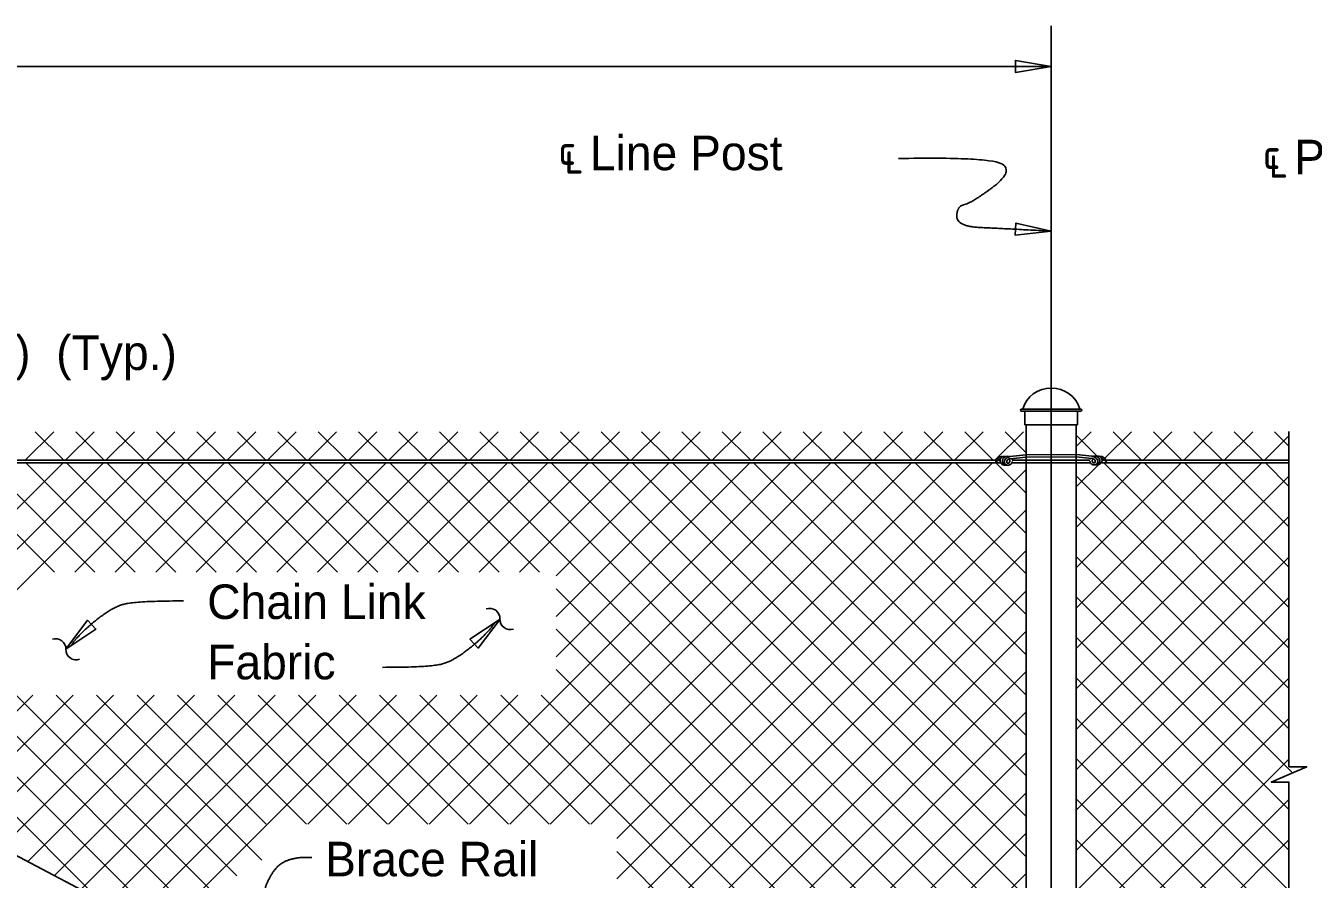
# Model space of a CAD drawing. Extents: x 0.5 to 39.7, y 0.9 to 25.6.
# Drawn here: x 16.23 to 23.73, y 20.53 to 25.5 of the extents above; entities that cross this region are included whole.
import ezdxf

# ---------------------------------------------------------------- set-up
doc = ezdxf.new("R2010")
doc.units = 0
for name, color, linetype in [('CL_Major', 7, 'Continuous'), ('Dimension', 7, 'Continuous'), ('Miscellaneous', 7, 'Continuous'), ('SteelMisc', 7, 'Continuous'), ('SteelMisc_h', 7, 'Continuous'), ('TextStructures', 7, 'Continuous')]:
    doc.layers.add(name, color=color, linetype=linetype)

msp = doc.modelspace()

# ---------------------------------------------------------------- linework, layer by layer
at = {"layer": 'CL_Major'}
msp.add_line((22.2062, 25.5043), (22.2062, 14.6639), dxfattribs=at)
at = {"layer": 'Dimension'}
msp.add_line((2.2062, 25.2672), (22.2062, 25.2672), dxfattribs=at)
for points in [[(22.2062, 25.2672), (21.998, 25.3025), (21.998, 25.2319)], [(22.2062, 24.3062), (22.0002, 24.3528), (21.9964, 24.2823)], [(16.4595, 21.8673), (16.6347, 21.9852), (16.5861, 22.0364)], [(18.9917, 22.0434), (18.8164, 21.9255), (18.865, 21.8743)]]:
    msp.add_lwpolyline(points, close=True, dxfattribs=at)
msp.add_lwpolyline([(23.5932, 23.1382), (23.5932, 21.1819), (23.6966, 21.1819), (23.5932, 21.1369), (23.4899, 21.0919), (23.5932, 21.0919), (23.5932, 20.1983)], dxfattribs=at)
for centre, start, end in [((18.9315, 22.0462), 357.71778, 109.44499), ((19.0506, 22.0414), 177.71778, 289.44499), ((16.4004, 21.8692), 357.71778, 109.44499), ((16.5195, 21.8645), 177.71778, 289.44499)]:
    msp.add_arc(centre, 0.0596, start, end, dxfattribs=at)
for points in [[(21.3167, 24.7299), (21.8625, 24.7397), (21.9849, 24.6508), (21.7407, 24.4695), (21.6558, 24.4512), (21.6558, 24.3333), (21.9339, 24.321), (22.2062, 24.3061)], [(17.1447, 22.149), (16.8545, 22.149), (16.7179, 22.1042), (16.5309, 21.9506), (16.4925, 21.893)], [(18.3063, 21.7616), (18.5965, 21.7616), (18.7331, 21.8064), (18.9201, 21.96), (18.9585, 22.0176)], [(17.894, 20.6524), (17.7375, 20.6606), (17.6194, 20.5021), (17.6164, 20.3809), (17.6211, 20.2132), (17.6839, 19.8645)]]:
    msp.add_open_spline(points, degree=2, dxfattribs=at)
at = {"layer": 'Miscellaneous'}
for p, q in [((16.2217, 22.9695), (16.3884, 23.1361)), ((16.281, 23.1361), (16.4476, 22.9695)), ((16.4575, 22.9695), (16.6241, 23.1361)), ((16.5167, 23.1361), (16.6833, 22.9695)), ((16.6932, 22.9695), (16.8598, 23.1361)), ((16.7524, 23.1361), (16.919, 22.9695)), ((16.9289, 22.9695), (17.0955, 23.1361)), ((16.9881, 23.1361), (17.1547, 22.9695)), ((17.1646, 22.9695), (17.3312, 23.1361)), ((17.2238, 23.1361), (17.3904, 22.9695)), ((17.4003, 22.9695), (17.5669, 23.1361)), ((17.4595, 23.1361), (17.6262, 22.9695)), ((17.636, 22.9695), (17.8026, 23.1361)), ((17.6952, 23.1361), (17.8619, 22.9695)), ((17.8717, 22.9695), (18.0383, 23.1361)), ((17.9309, 23.1361), (18.0976, 22.9695)), ((18.1074, 22.9695), (18.274, 23.1361)), ((18.1666, 23.1361), (18.3333, 22.9695)), ((18.3431, 22.9695), (18.5097, 23.1361)), ((18.4023, 23.1361), (18.569, 22.9695)), ((18.5788, 22.9695), (18.7454, 23.1361)), ((18.638, 23.1361), (18.8047, 22.9695)), ((18.8145, 22.9695), (18.9811, 23.1361)), ((18.8737, 23.1361), (19.0404, 22.9695)), ((19.0502, 22.9695), (19.2168, 23.1361)), ((19.1094, 23.1361), (19.2761, 22.9695)), ((19.2859, 22.9695), (19.4525, 23.1361)), ((19.3451, 23.1361), (19.5118, 22.9695)), ((19.5216, 22.9695), (19.6882, 23.1361)), ((19.5808, 23.1361), (19.7475, 22.9695)), ((19.7573, 22.9695), (19.9239, 23.1361)), ((19.8165, 23.1361), (19.9832, 22.9695)), ((19.993, 22.9695), (20.1597, 23.1361)), ((20.0522, 23.1361), (20.2189, 22.9695)), ((20.2287, 22.9695), (20.3954, 23.1361)), ((20.2879, 23.1361), (20.4546, 22.9695)), ((20.4644, 22.9695), (20.6311, 23.1361)), ((20.5236, 23.1361), (20.6903, 22.9695)), ((20.7001, 22.9695), (20.8668, 23.1361)), ((20.7593, 23.1361), (20.926, 22.9695)), ((20.9358, 22.9695), (21.1025, 23.1361)), ((20.995, 23.1361), (21.1617, 22.9695)), ((21.1715, 22.9695), (21.3382, 23.1361)), ((21.2307, 23.1361), (21.3974, 22.9695)), ((21.4072, 22.9695), (21.5739, 23.1361)), ((21.4664, 23.1361), (21.6331, 22.9695)), ((21.6429, 22.9695), (21.8096, 23.1361)), ((21.7021, 23.1361), (21.8688, 22.9695)), ((21.8786, 22.9695), (22.0453, 23.1361)), ((21.9378, 23.1361), (22.0604, 23.0136)), ((22.3521, 23.0495), (22.4386, 23.1361)), ((22.5192, 22.981), (22.6743, 23.1361)), ((22.5669, 23.1361), (22.7336, 22.9695)), ((22.7434, 22.9695), (22.91, 23.1361)), ((22.8026, 23.1361), (22.9693, 22.9695)), ((22.9791, 22.9695), (23.1458, 23.1361)), ((23.0383, 23.1361), (23.205, 22.9695)), ((23.2148, 22.9695), (23.3815, 23.1361)), ((23.274, 23.1361), (23.4407, 22.9695)), ((23.5097, 23.1361), (23.5931, 23.0527)), ((22.3521, 23.1153), (22.4743, 22.993)), ((23.4505, 22.9695), (23.5931, 23.1121)), ((14.1054, 22.9547), (16.6484, 20.4117)), ((14.3411, 22.9547), (17.1483, 20.1475)), ((14.5768, 22.9547), (17.4573, 20.0742)), ((14.8125, 22.9547), (17.4573, 20.3099)), ((14.85, 21.362), (16.4427, 22.9547)), ((15.0042, 21.2805), (16.6784, 22.9547)), ((15.1584, 21.199), (16.9141, 22.9547)), ((15.7553, 22.9547), (16.393, 22.317)), ((15.991, 22.9547), (16.6287, 22.317)), ((16.2267, 22.9547), (16.8644, 22.317)), ((16.4624, 22.9547), (17.1001, 22.317)), ((16.5121, 22.317), (17.1498, 22.9547)), ((16.6981, 22.9547), (17.3358, 22.317)), ((16.7478, 22.317), (17.3855, 22.9547)), ((16.9338, 22.9547), (17.5715, 22.317)), ((16.9835, 22.317), (17.6212, 22.9547)), ((17.1695, 22.9547), (17.8072, 22.317)), ((17.2192, 22.317), (17.8569, 22.9547)), ((17.4052, 22.9547), (18.0429, 22.317)), ((17.4549, 22.317), (18.0926, 22.9547)), ((17.6409, 22.9547), (18.2786, 22.317)), ((17.6906, 22.317), (18.3283, 22.9547)), ((17.8766, 22.9547), (18.5143, 22.317)), ((17.9263, 22.317), (18.564, 22.9547)), ((18.1123, 22.9547), (18.75, 22.317)), ((18.162, 22.317), (18.7997, 22.9547)), ((18.348, 22.9547), (18.9857, 22.317)), ((18.3977, 22.317), (19.0354, 22.9547)), ((18.5775, 20.8468), (20.6853, 22.9547)), ((18.5837, 22.9547), (19.2214, 22.317)), ((18.6334, 22.317), (19.2711, 22.9547)), ((18.8132, 20.8468), (20.921, 22.9547)), ((18.8194, 22.9547), (22.0604, 19.7137)), ((18.8691, 22.317), (19.5068, 22.9547)), ((19.0489, 20.8468), (21.1567, 22.9547)), ((19.0551, 22.9547), (22.0604, 19.9494)), ((19.1049, 22.317), (19.7425, 22.9547)), ((19.2846, 20.8468), (21.3924, 22.9547)), ((19.2908, 22.9547), (22.0604, 20.1851)), ((19.3184, 22.2948), (19.9782, 22.9547)), ((19.3184, 21.8234), (20.4496, 22.9547)), ((19.3184, 22.0591), (20.2139, 22.9547)), ((19.5203, 20.8468), (21.6282, 22.9547)), ((19.5203, 20.8468), (21.6282, 22.9547)), ((19.5265, 22.9547), (22.0604, 20.4208)), ((19.6731, 20.7639), (21.8639, 22.9547)), ((19.6731, 20.5282), (22.0604, 22.9155)), ((19.7622, 22.9547), (22.0604, 20.6565)), ((19.9979, 22.9547), (22.0604, 20.8922)), ((20.2336, 22.9547), (22.0604, 21.1279)), ((20.4693, 22.9547), (22.0604, 21.3636)), ((20.705, 22.9547), (22.0604, 21.5993)), ((20.9407, 22.9547), (22.0604, 21.835)), ((21.1764, 22.9547), (22.0604, 22.0707)), ((21.4121, 22.9547), (22.0604, 22.3064)), ((21.6478, 22.9547), (22.0604, 22.5421)), ((21.8835, 22.9547), (22.0604, 22.7779)), ((22.3521, 21.871), (23.4357, 22.9547)), ((22.3521, 22.3424), (22.9643, 22.9547)), ((22.3521, 22.5781), (22.7286, 22.9547)), ((22.3521, 22.8138), (22.4815, 22.9433)), ((22.3565, 22.1112), (23.2, 22.9547)), ((22.5077, 22.9695), (22.5121, 22.9739)), ((22.5126, 22.9547), (23.5931, 21.8742)), ((22.7483, 22.9547), (23.5931, 22.1099)), ((22.984, 22.9547), (23.5931, 22.3456)), ((23.2197, 22.9547), (23.5931, 22.5813)), ((23.4554, 22.9547), (23.5931, 22.817)), ((22.3521, 22.8796), (23.5931, 21.6385)), ((22.3521, 21.6353), (23.5931, 22.8764)), ((18.7053, 19.3247), (22.0604, 22.6798)), ((22.3521, 22.6439), (23.5931, 21.4028)), ((22.3521, 21.3996), (23.5931, 22.6407)), ((18.8595, 19.2432), (22.0604, 22.4441)), ((22.3521, 22.4082), (23.6142, 21.146)), ((22.3521, 21.1639), (23.5931, 22.405)), ((19.0137, 19.1617), (22.0604, 22.2084)), ((19.3184, 22.22), (22.0604, 19.478)), ((22.3521, 22.1725), (23.5931, 20.9314)), ((22.3521, 20.9282), (23.5931, 22.1693)), ((19.1679, 19.0802), (22.0604, 21.9727)), ((19.3184, 21.9843), (22.0604, 19.2423)), ((22.3521, 21.9368), (23.5931, 20.6957)), ((22.3521, 20.6925), (23.5931, 21.9336)), ((19.3184, 21.7486), (22.0604, 19.0066)), ((19.3221, 18.9987), (22.0604, 21.737)), ((22.3521, 21.701), (23.5931, 20.46)), ((22.3521, 20.4568), (23.5931, 21.6979)), ((15.6211, 20.9546), (16.2665, 21.6)), ((15.7753, 20.8731), (16.5022, 21.6)), ((15.7753, 20.8731), (16.5022, 21.6)), ((15.9295, 20.7916), (16.7379, 21.6)), ((15.9295, 20.7916), (16.7379, 21.6)), ((16.0837, 20.7101), (16.9736, 21.6)), ((16.0837, 20.7101), (16.9736, 21.6)), ((16.2379, 20.6286), (17.2093, 21.6)), ((16.2379, 20.6286), (17.2093, 21.6)), ((16.3921, 20.5471), (17.445, 21.6)), ((16.4029, 21.6), (17.4573, 20.5456)), ((16.5463, 20.4656), (17.6807, 21.6)), ((16.6386, 21.6), (17.6017, 20.6369)), ((16.7005, 20.3841), (17.9164, 21.6)), ((16.8547, 20.3026), (18.1521, 21.6)), ((16.8743, 21.6), (17.6275, 20.8468)), ((16.8743, 21.6), (17.6275, 20.8468)), ((17.009, 20.2211), (18.3878, 21.6)), ((17.11, 21.6), (17.8632, 20.8468)), ((17.3457, 21.6), (18.0989, 20.8468)), ((17.3457, 21.6), (18.0989, 20.8468)), ((17.3457, 21.6), (18.0989, 20.8468)), ((17.5814, 21.6), (18.3346, 20.8468)), ((17.5814, 21.6), (18.3346, 20.8468)), ((17.8171, 21.6), (18.5703, 20.8468)), ((17.8704, 20.8468), (18.6235, 21.6)), ((18.0528, 21.6), (18.806, 20.8468)), ((18.1061, 20.8468), (18.8592, 21.6)), ((18.2885, 21.6), (19.0417, 20.8468)), ((18.3418, 20.8468), (19.0949, 21.6)), ((18.5242, 21.6), (19.2774, 20.8468)), ((18.7599, 21.6), (19.5131, 20.8468)), ((18.9956, 21.6), (22.0604, 18.5352)), ((19.2313, 21.6), (22.0604, 18.7709)), ((19.4763, 18.9172), (22.0604, 21.5013)), ((22.3521, 21.4653), (23.5931, 20.2243)), ((22.3521, 20.2211), (23.5931, 21.4622)), ((19.6305, 18.8357), (22.0604, 21.2656)), ((22.3521, 21.2296), (23.5931, 19.9886)), ((22.3521, 19.9854), (23.5931, 21.2265)), ((19.7847, 18.7543), (22.0604, 21.0299)), ((22.3521, 20.9939), (23.5931, 19.7529)), ((22.3521, 19.7497), (23.5931, 20.9908)), ((19.9389, 18.6728), (22.0604, 20.7942)), ((22.3521, 20.7582), (23.5931, 19.5171)), ((22.3521, 19.514), (23.5931, 20.7551)), ((19.6731, 20.6868), (22.0604, 18.2995)), ((20.0931, 18.5913), (22.0604, 20.5585))]:
    msp.add_line(p, q, dxfattribs=at)
at = {"layer": 'SteelMisc'}
for p, q in [((22.034, 23.2681), (22.3785, 23.2681)), ((22.3785, 23.2559), (22.034, 23.2559)), ((22.0522, 23.1761), (22.0522, 23.2559)), ((22.3603, 23.1761), (22.3603, 23.2559)), ((22.3603, 23.1761), (22.0522, 23.1761)), ((22.0604, 17.5309), (22.0604, 23.1761)), ((22.3521, 17.5309), (22.3521, 23.1761)), ((22.0604, 23.0021), (21.9655, 22.991)), ((22.0604, 22.9876), (21.9678, 22.978)), ((22.0604, 23.0021), (22.3516, 23.0038)), ((22.0604, 22.9876), (22.3516, 22.9892)), ((22.3516, 23.0038), (22.4459, 22.9926)), ((22.3516, 22.9892), (22.4437, 22.9798)), ((13.4503, 22.9695), (21.8852, 22.9695)), ((13.4503, 22.9547), (21.9119, 22.9547)), ((21.8952, 22.9695), (21.9083, 22.9695)), ((21.9768, 22.9547), (22.0604, 22.9547)), ((21.9782, 22.9695), (22.0604, 22.9695)), ((22.3521, 22.9695), (22.4325, 22.9695)), ((22.3521, 22.9547), (22.4351, 22.9547)), ((22.4979, 22.9547), (23.5931, 22.9547)), ((22.5028, 22.9695), (22.518, 22.9695)), ((22.5265, 22.9695), (23.5931, 22.9695)), ((21.8588, 17.6582), (12.6092, 22.5462))]:
    msp.add_line(p, q, dxfattribs=at)
for centre, start, end in [((22.034, 23.2618), 91.1647, 268.8353), ((22.3784, 23.2618), 271.1647, 88.8353)]:
    msp.add_arc(centre, 0.00613, start, end, dxfattribs=at)
for centre, major_axis, ratio, start_param, end_param in [((22.2069, 23.227), (0.1711, 0), 0.957868, 0.252602, 2.888574), ((21.9195, 22.9552), (0.0373, 0), 0.957868, 1.486836, 3.108042), ((21.932, 22.9697), (0.023, 0), 0.957868, 1.29026, 2.970541), ((21.9507, 22.9643), (0.0295, 0), 0.957868, 1.220941, 4.039556), ((21.9642, 22.9661), (-0.0303, -0.0108), 0.724765, 4.35367, 6.324556), ((22.4573, 22.966), (-0.0251, 0), 0.957868, 5.673972, 5.875498), ((22.4418, 22.9549), (0.0259, 0), 0.957868, 0.655696, 1.505671), ((22.4468, 22.9678), (0.0303, -0.0108), 0.724765, 6.241815, 8.212701), ((22.4603, 22.9661), (-0.0295, 0), 0.957868, 2.243629, 5.062245), ((22.479, 22.9714), (-0.023, 0), 0.957868, 3.312645, 4.992926), ((22.4915, 22.957), (-0.0373, 0), 0.957868, 3.175144, 4.79635), ((22.4704, 22.9173), (0.0724, 0), 0.957868, 0.631079, 1.121037), ((21.9406, 22.9155), (-0.0724, 0), 0.957868, 5.162149, 5.652106), ((21.9331, 22.9671), (-0.0249, 0), 0.957868, 6.009018, 7.089857), ((21.9345, 22.9631), (0.0231, 0), 0.957868, 3.779554, 4.879821), ((21.9406, 22.9575), (0.0206, -0.0021), 0.798607, 4.32653, 5.220153), ((21.9541, 22.9575), (0.0206, -0.0021), 0.798607, 3.333154, 5.220153), ((21.9609, 22.962), (-0.0139, 0), 0.957868, 5.22362, 6.905413), ((21.9552, 22.9596), (-0.00795, 0), 0.957868, 6.140374, 9.314262), ((21.9693, 22.9532), (-0.0259, 0), 0.957868, 4.777514, 5.62749), ((21.9535, 22.9654), (0.0119, 0), 0.957868, 5.725876, 7.416677), ((21.9467, 22.9762), (0.0391, 0), 0.957868, 5.082588, 5.41974), ((21.9535, 22.9654), (0.0119, 0), 0.957868, 5.639684, 5.723117), ((21.9535, 22.9654), (0.0119, 0), 0.957868, 5.639684, 5.723117), ((21.9538, 22.9642), (0.0251, 0), 0.957868, 5.531357, 6.227833), ((21.9538, 22.9642), (0.0251, 0), 0.957868, 0.407687, 0.609214), ((22.4573, 22.966), (-0.0251, 0), 0.957868, 0.055352, 0.751829), ((22.4643, 22.978), (-0.0391, 0), 0.957868, 0.863445, 1.200597), ((22.4575, 22.9672), (-0.0119, 0), 0.957868, 5.149694, 6.840495), ((22.4575, 22.9672), (-0.0119, 0), 0.957868, 0.560069, 0.643501), ((22.4558, 22.9614), (0.00795, 0), 0.957868, 3.252108, 6.425997), ((22.4569, 22.9592), (-0.0206, -0.0021), 0.798607, 1.063032, 2.950031), ((22.4501, 22.9638), (0.0139, 0), 0.957868, 5.660958, 7.342751), ((22.4704, 22.9592), (-0.0206, -0.0021), 0.798607, 1.063032, 1.956656), ((22.4765, 22.9649), (-0.0231, 0), 0.957868, 1.403365, 2.503632), ((22.4779, 22.9689), (0.0249, 0), 0.957868, 5.476514, 6.557353)]:
    msp.add_ellipse(centre, major_axis=major_axis, ratio=ratio, start_param=start_param, end_param=end_param, dxfattribs=at)
at = {"layer": 'SteelMisc_h'}
for p, q in [((22.0604, 22.9695), (22.3521, 22.9695)), ((22.0604, 22.9547), (22.3521, 22.9547))]:
    msp.add_line(p, q, dxfattribs=at)

# ---------------------------------------------------------------- texts
at = {"layer": 'Dimension'}
for s, p in [('Chain Link ', (17.2835, 22.0436)), ('Fabric ', (17.2835, 21.6916))]:
    msp.add_text(s, height=0.2016, dxfattribs=at).set_placement(p)
at = {"layer": 'TextStructures'}
for s, p in [('℄ Line Post', (19.3313, 24.6617)), ('℄ Pull Post', (23.4401, 24.6377)), ('Varies (1\'-0" Max.)  (Typ.)', (14.0385, 23.4963)), ('Brace Rail', (17.9713, 20.5425))]:
    msp.add_text(s, height=0.2016, dxfattribs=at).set_placement(p)

doc.saveas('drawing.dxf')
